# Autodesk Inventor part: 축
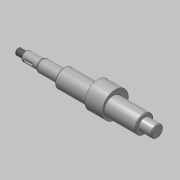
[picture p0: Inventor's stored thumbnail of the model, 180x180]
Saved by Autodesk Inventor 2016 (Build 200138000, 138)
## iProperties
Created: 2015-12
Part Number: 축
Document SubType Name: Modeling
Designer: mdu
Density: 7.86 g/cm^3
Material: 강철, 연강
Appearance: 강철
Mass: 489.929 g
Surface Area: 127.026 cm^2
Volume: 62.332 cm^3
Author: mdu
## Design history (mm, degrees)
sketch "스케치1"
  geometry: L1 (62, 100.9)-(62, 67.1) reference; L2 (51, 101.2)-(51, 84) reference; L3 (-51, 84)-(-51, 101.2) reference; L4 (-62, 67.1)-(-62, 100.9) reference; L5 (-51.6, 91.5)-(-61.4, 91.5) reference; L6 (51.6, 91.5)-(61.4, 91.5) reference; L7 (67, 84)-(-109, 84); L8 (-77, 64.201)-(-77, 103.799) reference; L9 (67, 84)-(67, 91.5); L10 (67, 91.5)-(51, 91.5); L11 (51, 91.5)-(51, 95.5); L12 (51, 95.5)-(-51, 95.5); L13 (-51, 95.5)-(-51, 91.5); L14 (-51, 91.5)-(-79, 91.5); L15 (-79, 91.5)-(-79, 90); L16 (-79, 90)-(-99, 90); L17 (-99, 90)-(-99, 88); L18 (-99, 88)-(-109, 88); L19 (-109, 88)-(-109, 84); 2 further points
  constraints: 28 end point, 7 parallel, 5 point on line, 4 perpendicular, 2 collinear, 2 horizontal, 1 midpoint, 4 other
  dimensions: "d0" = 5 distance from line of L7.start L1; "d2" = 2 distance between parallel lines of L15 L8; "d3" = 23 diameter of L12 L7; "d4" = 12 diameter of L16 L7; "d7" = 20 distance of L15.end L16.end; "d8" = 10 distance between parallel lines of L17 L19; "d9" = 8 diameter of L18 L7
revolve "회전1" sketch "스케치1" stored, may be unused: angle "d10" = 90 deg
sketch "스케치2"
  geometry: C1 r 11.5 at (84, 0) reference; C2 r 11.5 at (84, 0) reference; C3 r 16.5 at (87, 0); 1 further point
  constraints: 1 centre point, 1 horizontal alignment
  dimensions: "d11" = 33 diameter of C3; "d12" = 3 distance of C3.centre C1.centre
extrude "돌출1" join sketch "스케치2" stored distance "d13" = 22; taper "d14" = 0 deg
chamfer "모따기1" distance "d15" = 1; stored, may be unused: second distance "d16" = 2, angle "d17" = 45 deg
feature "스레드1" dims "d18" = 8, "d19" = 0
node "작업 평면1"
sketch "스케치3"
  geometry: L1 (-5, -2)-(3, -2); L2 (3, 2)-(-5, 2); L3 (-10, -5)-(-10, 5) reference; A1 r 2 centre (3, 0) between (3, -2) and (3, 2); A2 r 2 centre (-5, 0) between (-5, 2) and (-5, -2); 2 further points
  constraints: 4 end point, 4 point on circle, 4 tangent, 2 centre point, 1 horizontal, 1 horizontal alignment, 1 midpoint, 1 parallel
  dimensions: "d20" = 4 distance between parallel lines of L1 L2; "d21" = 12 dimension on A1 A2; "d22" = 3 distance edge to line of A2 L3
extrude "돌출2" cut sketch "스케치3" distance "d23" = 2.5; taper "d24" = 0 deg
fillet "모깎기1" dims "d25" = 0.3
chamfer "모따기2" distance "d27" = 1.65; stored, may be unused: second distance "d28" = 2, angle "d29" = 30 deg
fillet "모깎기3" dims "d30" = 2
node "솔리드1"
node "참조1"
node "참조2"
node "참조3"
node "참조4"
node "참조5"
node "투영된 루프1"
